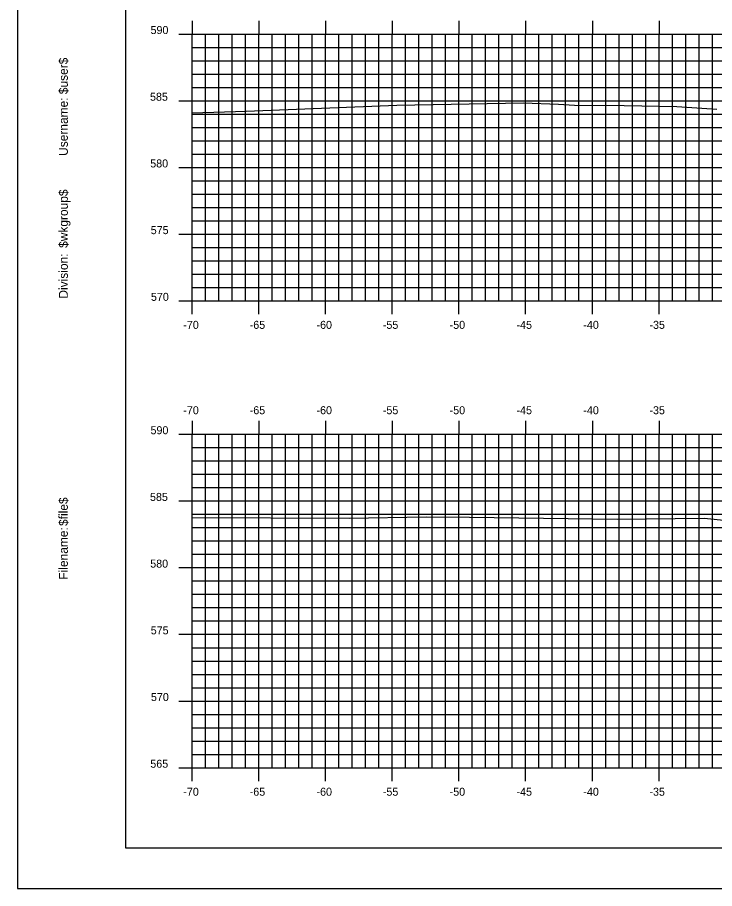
# Model space of a CAD drawing. Extents: x 1047919 to 1048089, y 779716 to 779826.
# Drawn here: x 1047918.9 to 1047971.1, y 779715.6 to 779781 of the extents above; entities that cross this region are included whole.
import ezdxf

# ---------------------------------------------------------------- set-up
doc = ezdxf.new("R2010")
doc.units = 0
for name, color, linetype in [('BORDER', 7, 'Continuous'), ('H_V ANNOTATION', 7, 'Continuous'), ('MAJOR', 7, 'Continuous'), ('MINOR', 7, 'Continuous'), ('PLOT BOUNDARY', 7, 'Continuous'), ('S_Roadway_Centerline', 7, 'Continuous')]:
    doc.layers.add(name, color=color, linetype=linetype)

msp = doc.modelspace()

# ---------------------------------------------------------------- linework, layer by layer
at = {"layer": 'BORDER'}
msp.add_lwpolyline([(1047926.957, 779718.706), (1048086.957, 779718.706), (1048086.957, 779823.706), (1047926.957, 779823.706)], close=True, dxfattribs=at)
at = {"layer": 'MAJOR'}
for p, q in [((1047931.956, 779780.708), (1047931.956, 779779.706)), ((1047936.956, 779780.708), (1047936.956, 779779.706)), ((1047941.956, 779780.708), (1047941.956, 779779.706)), ((1047946.956, 779780.708), (1047946.956, 779779.706)), ((1047951.956, 779780.708), (1047951.956, 779779.706)), ((1047956.956, 779780.708), (1047956.956, 779779.706)), ((1047961.956, 779780.708), (1047961.956, 779779.706)), ((1047966.956, 779780.708), (1047966.956, 779779.706)), ((1047930.954, 779779.706), (1047931.956, 779779.706)), ((1047931.956, 779779.706), (1048071.956, 779779.706)), ((1047931.956, 779759.706), (1047931.956, 779779.706)), ((1047931.956, 779759.706), (1047931.956, 779779.706)), ((1047931.956, 779779.706), (1048071.956, 779779.706)), ((1047936.956, 779759.706), (1047936.956, 779779.706)), ((1047941.956, 779759.706), (1047941.956, 779779.706)), ((1047946.956, 779759.706), (1047946.956, 779779.706)), ((1047951.956, 779759.706), (1047951.956, 779779.706)), ((1047956.956, 779759.706), (1047956.956, 779779.706)), ((1047961.956, 779759.706), (1047961.956, 779779.706)), ((1047966.956, 779759.706), (1047966.956, 779779.706)), ((1047930.954, 779774.706), (1047931.956, 779774.706)), ((1047931.956, 779774.706), (1048071.956, 779774.706)), ((1047930.954, 779769.706), (1047931.956, 779769.706)), ((1047931.956, 779769.706), (1048071.956, 779769.706)), ((1047930.954, 779764.706), (1047931.956, 779764.706)), ((1047931.956, 779764.706), (1048071.956, 779764.706)), ((1047930.954, 779759.706), (1047931.956, 779759.706)), ((1047931.956, 779759.706), (1048071.956, 779759.706)), ((1047931.956, 779759.706), (1048071.956, 779759.706)), ((1047931.956, 779758.704), (1047931.956, 779759.706)), ((1047936.956, 779758.704), (1047936.956, 779759.706)), ((1047941.956, 779758.704), (1047941.956, 779759.706)), ((1047946.956, 779758.704), (1047946.956, 779759.706)), ((1047951.956, 779758.704), (1047951.956, 779759.706)), ((1047956.956, 779758.704), (1047956.956, 779759.706)), ((1047961.956, 779758.704), (1047961.956, 779759.706)), ((1047966.956, 779758.704), (1047966.956, 779759.706)), ((1047931.956, 779750.708), (1047931.956, 779749.706)), ((1047936.956, 779750.708), (1047936.956, 779749.706)), ((1047941.956, 779750.708), (1047941.956, 779749.706)), ((1047946.956, 779750.708), (1047946.956, 779749.706)), ((1047951.956, 779750.708), (1047951.956, 779749.706)), ((1047956.956, 779750.708), (1047956.956, 779749.706)), ((1047961.956, 779750.708), (1047961.956, 779749.706)), ((1047966.956, 779750.708), (1047966.956, 779749.706)), ((1047930.954, 779749.706), (1047931.956, 779749.706)), ((1047931.956, 779749.706), (1048071.956, 779749.706)), ((1047931.956, 779724.706), (1047931.956, 779749.706)), ((1047931.956, 779724.706), (1047931.956, 779749.706)), ((1047931.956, 779749.706), (1048071.956, 779749.706)), ((1047936.956, 779724.706), (1047936.956, 779749.706)), ((1047941.956, 779724.706), (1047941.956, 779749.706)), ((1047946.956, 779724.706), (1047946.956, 779749.706)), ((1047951.956, 779724.706), (1047951.956, 779749.706)), ((1047956.956, 779724.706), (1047956.956, 779749.706)), ((1047961.956, 779724.706), (1047961.956, 779749.706)), ((1047966.956, 779724.706), (1047966.956, 779749.706)), ((1047930.954, 779744.706), (1047931.956, 779744.706)), ((1047931.956, 779744.706), (1048071.956, 779744.706)), ((1047930.954, 779739.706), (1047931.956, 779739.706)), ((1047931.956, 779739.706), (1048071.956, 779739.706)), ((1047930.954, 779734.706), (1047931.956, 779734.706)), ((1047931.956, 779734.706), (1048071.956, 779734.706)), ((1047930.954, 779729.706), (1047931.956, 779729.706)), ((1047931.956, 779729.706), (1048071.956, 779729.706)), ((1047930.954, 779724.706), (1047931.956, 779724.706)), ((1047931.956, 779724.706), (1048071.956, 779724.706)), ((1047931.956, 779724.706), (1048071.956, 779724.706)), ((1047931.956, 779723.704), (1047931.956, 779724.706)), ((1047936.956, 779723.704), (1047936.956, 779724.706)), ((1047941.956, 779723.704), (1047941.956, 779724.706)), ((1047946.956, 779723.704), (1047946.956, 779724.706)), ((1047951.956, 779723.704), (1047951.956, 779724.706)), ((1047956.956, 779723.704), (1047956.956, 779724.706)), ((1047961.956, 779723.704), (1047961.956, 779724.706)), ((1047966.956, 779723.704), (1047966.956, 779724.706))]:
    msp.add_line(p, q, dxfattribs=at)
at = {"layer": 'MINOR'}
for p, q in [((1047932.956, 779759.706), (1047932.956, 779779.706)), ((1047933.956, 779759.706), (1047933.956, 779779.706)), ((1047934.956, 779759.706), (1047934.956, 779779.706)), ((1047935.956, 779759.706), (1047935.956, 779779.706)), ((1047937.956, 779759.706), (1047937.956, 779779.706)), ((1047938.956, 779759.706), (1047938.956, 779779.706)), ((1047939.956, 779759.706), (1047939.956, 779779.706)), ((1047940.956, 779759.706), (1047940.956, 779779.706)), ((1047942.956, 779759.706), (1047942.956, 779779.706)), ((1047943.956, 779759.706), (1047943.956, 779779.706)), ((1047944.956, 779759.706), (1047944.956, 779779.706)), ((1047945.956, 779759.706), (1047945.956, 779779.706)), ((1047947.956, 779759.706), (1047947.956, 779779.706)), ((1047948.956, 779759.706), (1047948.956, 779779.706)), ((1047949.956, 779759.706), (1047949.956, 779779.706)), ((1047950.956, 779759.706), (1047950.956, 779779.706)), ((1047952.956, 779759.706), (1047952.956, 779779.706)), ((1047953.956, 779759.706), (1047953.956, 779779.706)), ((1047954.956, 779759.706), (1047954.956, 779779.706)), ((1047955.956, 779759.706), (1047955.956, 779779.706)), ((1047957.956, 779759.706), (1047957.956, 779779.706)), ((1047958.956, 779759.706), (1047958.956, 779779.706)), ((1047959.956, 779759.706), (1047959.956, 779779.706)), ((1047960.956, 779759.706), (1047960.956, 779779.706)), ((1047962.956, 779759.706), (1047962.956, 779779.706)), ((1047963.956, 779759.706), (1047963.956, 779779.706)), ((1047964.956, 779759.706), (1047964.956, 779779.706)), ((1047965.956, 779759.706), (1047965.956, 779779.706)), ((1047967.956, 779759.706), (1047967.956, 779779.706)), ((1047968.956, 779759.706), (1047968.956, 779779.706)), ((1047969.956, 779759.706), (1047969.956, 779779.706)), ((1047970.956, 779759.706), (1047970.956, 779779.706)), ((1047931.956, 779778.706), (1048071.956, 779778.706)), ((1047931.956, 779778.706), (1047932.958, 779778.706)), ((1047931.956, 779777.706), (1048071.956, 779777.706)), ((1047931.956, 779777.706), (1047932.958, 779777.706)), ((1047931.956, 779776.706), (1048071.956, 779776.706)), ((1047931.956, 779776.706), (1047932.958, 779776.706)), ((1047931.956, 779775.706), (1048071.956, 779775.706)), ((1047931.956, 779775.706), (1047932.958, 779775.706)), ((1047931.956, 779773.706), (1048071.956, 779773.706)), ((1047931.956, 779773.706), (1047932.958, 779773.706)), ((1047931.956, 779772.706), (1048071.956, 779772.706)), ((1047931.956, 779772.706), (1047932.958, 779772.706)), ((1047931.956, 779771.706), (1048071.956, 779771.706)), ((1047931.956, 779771.706), (1047932.958, 779771.706)), ((1047931.956, 779770.706), (1048071.956, 779770.706)), ((1047931.956, 779770.706), (1047932.958, 779770.706)), ((1047931.956, 779768.706), (1048071.956, 779768.706)), ((1047931.956, 779768.706), (1047932.958, 779768.706)), ((1047931.956, 779767.706), (1048071.956, 779767.706)), ((1047931.956, 779767.706), (1047932.958, 779767.706)), ((1047931.956, 779766.706), (1048071.956, 779766.706)), ((1047931.956, 779766.706), (1047932.958, 779766.706)), ((1047931.956, 779765.706), (1048071.956, 779765.706)), ((1047931.956, 779765.706), (1047932.958, 779765.706)), ((1047931.956, 779763.706), (1048071.956, 779763.706)), ((1047931.956, 779763.706), (1047932.958, 779763.706)), ((1047931.956, 779762.706), (1048071.956, 779762.706)), ((1047931.956, 779762.706), (1047932.958, 779762.706)), ((1047931.956, 779761.706), (1048071.956, 779761.706)), ((1047931.956, 779761.706), (1047932.958, 779761.706)), ((1047931.956, 779760.706), (1048071.956, 779760.706)), ((1047931.956, 779760.706), (1047932.958, 779760.706)), ((1047931.956, 779724.706), (1047931.956, 779749.706)), ((1047932.956, 779724.706), (1047932.956, 779749.706)), ((1047933.956, 779724.706), (1047933.956, 779749.706)), ((1047934.956, 779724.706), (1047934.956, 779749.706)), ((1047935.956, 779724.706), (1047935.956, 779749.706)), ((1047937.956, 779724.706), (1047937.956, 779749.706)), ((1047938.956, 779724.706), (1047938.956, 779749.706)), ((1047939.956, 779724.706), (1047939.956, 779749.706)), ((1047940.956, 779724.706), (1047940.956, 779749.706)), ((1047942.956, 779724.706), (1047942.956, 779749.706)), ((1047943.956, 779724.706), (1047943.956, 779749.706)), ((1047944.956, 779724.706), (1047944.956, 779749.706)), ((1047945.956, 779724.706), (1047945.956, 779749.706)), ((1047947.956, 779724.706), (1047947.956, 779749.706)), ((1047948.956, 779724.706), (1047948.956, 779749.706)), ((1047949.956, 779724.706), (1047949.956, 779749.706)), ((1047950.956, 779724.706), (1047950.956, 779749.706)), ((1047952.956, 779724.706), (1047952.956, 779749.706)), ((1047953.956, 779724.706), (1047953.956, 779749.706)), ((1047954.956, 779724.706), (1047954.956, 779749.706)), ((1047955.956, 779724.706), (1047955.956, 779749.706)), ((1047957.956, 779724.706), (1047957.956, 779749.706)), ((1047958.956, 779724.706), (1047958.956, 779749.706)), ((1047959.956, 779724.706), (1047959.956, 779749.706)), ((1047960.956, 779724.706), (1047960.956, 779749.706)), ((1047962.956, 779724.706), (1047962.956, 779749.706)), ((1047963.956, 779724.706), (1047963.956, 779749.706)), ((1047964.956, 779724.706), (1047964.956, 779749.706)), ((1047965.956, 779724.706), (1047965.956, 779749.706)), ((1047967.956, 779724.706), (1047967.956, 779749.706)), ((1047968.956, 779724.706), (1047968.956, 779749.706)), ((1047969.956, 779724.706), (1047969.956, 779749.706)), ((1047970.956, 779724.706), (1047970.956, 779749.706)), ((1047931.956, 779748.706), (1048071.956, 779748.706)), ((1047931.956, 779748.706), (1047932.958, 779748.706)), ((1047931.956, 779747.706), (1048071.956, 779747.706)), ((1047931.956, 779747.706), (1047932.958, 779747.706)), ((1047931.956, 779746.706), (1048071.956, 779746.706)), ((1047931.956, 779746.706), (1047932.958, 779746.706)), ((1047931.956, 779745.706), (1048071.956, 779745.706)), ((1047931.956, 779745.706), (1047932.958, 779745.706)), ((1047931.956, 779743.706), (1048071.956, 779743.706)), ((1047931.956, 779743.706), (1047932.958, 779743.706)), ((1047931.956, 779742.706), (1048071.956, 779742.706)), ((1047931.956, 779742.706), (1047932.958, 779742.706)), ((1047931.956, 779741.706), (1048071.956, 779741.706)), ((1047931.956, 779741.706), (1047932.958, 779741.706)), ((1047931.956, 779740.706), (1048071.956, 779740.706)), ((1047931.956, 779740.706), (1047932.958, 779740.706)), ((1047931.956, 779738.706), (1048071.956, 779738.706)), ((1047931.956, 779738.706), (1047932.958, 779738.706)), ((1047931.956, 779737.706), (1048071.956, 779737.706)), ((1047931.956, 779737.706), (1047932.958, 779737.706)), ((1047931.956, 779736.706), (1048071.956, 779736.706)), ((1047931.956, 779736.706), (1047932.958, 779736.706)), ((1047931.956, 779735.706), (1048071.956, 779735.706)), ((1047931.956, 779735.706), (1047932.958, 779735.706)), ((1047931.956, 779733.706), (1048071.956, 779733.706)), ((1047931.956, 779733.706), (1047932.958, 779733.706)), ((1047931.956, 779732.706), (1048071.956, 779732.706)), ((1047931.956, 779732.706), (1047932.958, 779732.706)), ((1047931.956, 779731.706), (1048071.956, 779731.706)), ((1047931.956, 779731.706), (1047932.958, 779731.706)), ((1047931.956, 779730.706), (1048071.956, 779730.706)), ((1047931.956, 779730.706), (1047932.958, 779730.706)), ((1047931.956, 779728.706), (1048071.956, 779728.706)), ((1047931.956, 779728.706), (1047932.958, 779728.706)), ((1047931.956, 779727.706), (1048071.956, 779727.706)), ((1047931.956, 779727.706), (1047932.958, 779727.706)), ((1047931.956, 779726.706), (1048071.956, 779726.706)), ((1047931.956, 779726.706), (1047932.958, 779726.706)), ((1047931.956, 779725.706), (1048071.956, 779725.706)), ((1047931.956, 779725.706), (1047932.958, 779725.706))]:
    msp.add_line(p, q, dxfattribs=at)
at = {"layer": 'PLOT BOUNDARY'}
msp.add_lwpolyline([(1047918.863, 779715.646), (1048088.863, 779715.646), (1048088.863, 779825.646), (1047918.863, 779825.646)], close=True, dxfattribs=at)
at = {"layer": 'S_Roadway_Centerline'}
for points in [[(1047931.956, 779773.808), (1047936.004, 779773.916), (1047947.302, 779774.378), (1047956.806, 779774.56), (1047959.429, 779774.44), (1047960.617, 779774.369), (1047964.35, 779774.358), (1047968.298, 779774.278), (1047971.279, 779774.083)], [(1047931.956, 779743.453), (1047943.724, 779743.414), (1047949.493, 779743.51), (1047952.756, 779743.487), (1047963.854, 779743.339), (1047970.33, 779743.413), (1047976.489, 779742.784), (1047976.843, 779742.779), (1047976.934, 779742.755), (1047978.299, 779742.547), (1047981.332, 779742.056), (1047981.486, 779741.882), (1047982, 779741.643), (1047982.001, 779741.64), (1047985.614, 779741.789), (1047989.569, 779741.982), (1047998.68, 779742.138), (1048001.705, 779742.215), (1048004.348, 779742.138), (1048013.473, 779741.93), (1048019.033, 779741.688), (1048021.766, 779741.578), (1048030.574, 779740.189)]]:
    msp.add_lwpolyline(points, dxfattribs=at)

# ---------------------------------------------------------------- texts
at = {"layer": 'BORDER'}
for s, p in [('$user$', (1047922.641, 779775.197)), ('Username:', (1047922.641, 779770.573)), ('$wkgroup$', (1047922.641, 779763.675)), ('Division:', (1047922.641, 779759.872)), ('$file$', (1047922.641, 779742.831)), ('Filename:', (1047922.641, 779738.804))]:
    msp.add_text(s, height=0.6696, rotation=90, dxfattribs=at).set_placement(p)
at = {"layer": 'H_V ANNOTATION'}
for s, p in [('590', (1047928.84, 779779.706)), ('585', (1047928.802, 779774.706)), ('580', (1047928.818, 779769.706)), ('575', (1047928.856, 779764.706)), ('570', (1047928.872, 779759.706)), ('-70', (1047931.298, 779757.606)), ('-65', (1047936.274, 779757.606)), ('-60', (1047941.282, 779757.606)), ('-55', (1047946.253, 779757.606)), ('-50', (1047951.261, 779757.606)), ('-45', (1047956.274, 779757.606)), ('-40', (1047961.282, 779757.606)), ('-35', (1047966.237, 779757.606)), ('-70', (1047931.298, 779751.206)), ('-65', (1047936.274, 779751.206)), ('-60', (1047941.282, 779751.206)), ('-55', (1047946.253, 779751.206)), ('-50', (1047951.261, 779751.206)), ('-45', (1047956.274, 779751.206)), ('-40', (1047961.282, 779751.206)), ('-35', (1047966.237, 779751.206)), ('590', (1047928.84, 779749.706)), ('585', (1047928.802, 779744.706)), ('580', (1047928.818, 779739.706)), ('575', (1047928.856, 779734.706)), ('570', (1047928.872, 779729.706)), ('565', (1047928.824, 779724.706)), ('-70', (1047931.298, 779722.606)), ('-65', (1047936.274, 779722.606)), ('-60', (1047941.282, 779722.606)), ('-55', (1047946.253, 779722.606)), ('-50', (1047951.261, 779722.606)), ('-45', (1047956.274, 779722.606)), ('-40', (1047961.282, 779722.606)), ('-35', (1047966.237, 779722.606))]:
    msp.add_text(s, height=0.6, dxfattribs=at).set_placement(p)
at = {"layer": 'MAJOR'}
for p in [(1047931.952, 779759.706), (1047931.952, 779724.706)]:
    msp.add_text('-', height=0.006, dxfattribs=at).set_placement(p)

doc.saveas('drawing.dxf')
